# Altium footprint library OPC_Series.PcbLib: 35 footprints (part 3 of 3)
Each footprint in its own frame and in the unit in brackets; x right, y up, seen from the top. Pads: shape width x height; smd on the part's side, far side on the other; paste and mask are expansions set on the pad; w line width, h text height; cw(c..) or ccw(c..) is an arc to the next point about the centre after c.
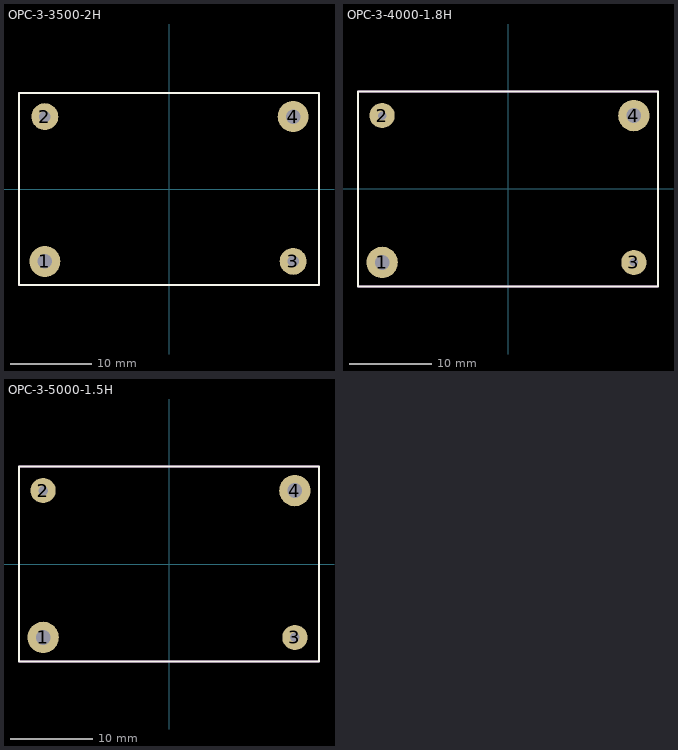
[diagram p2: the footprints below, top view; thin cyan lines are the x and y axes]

## OPC-3-3500-2H [mil]
pads (4):
  round 150 hole 70: 1(-600,-350) 4(600,350)
  round 130 hole 56: 2(-600,350) 3(600,-350)
Top Overlay:
  lines w10: -725,-465 725,-465 725,110 725,465 -725,465 -725,110 -725,-465
Mechanical 29:
  lines w10: -725,-465 725,-465 725,110 725,465 -725,465 -725,110 -725,-465
  text "'.Designator'" at -1750,-64.85 h400

## OPC-3-4000-1.8H [mil]
pads (4):
  round 150 hole 70: 1(-600,-350) 4(600,350)
  round 120 hole 40: 2(-600,350) 3(600,-350)
Top Overlay:
  lines w10: -715,-465 715,-465 715,110 715,465 -715,465 -715,-465
Mechanical 29:
  lines w10: -715,-465 715,-465 715,110 715,465 -715,465 -715,-465
  text "'.Designator'" at -1750,-64.85 h400

## OPC-3-5000-1.5H [mil]
pads (4):
  round 150 hole 70: 1(-600,-350) 4(600,350)
  round 120 hole 45: 2(-600,350) 3(600,-350)
Top Overlay:
  lines w10: -715,-465 -715,110 -715,465 715,465 715,110 715,-465 -715,-465
Mechanical 29:
  lines w10: -715,-465 -715,110 -715,465 715,465 715,110 715,-465 -715,-465
  text "'.Designator'" at -1750,-64.85 h400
